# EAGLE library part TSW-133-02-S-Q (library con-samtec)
THROUGH-HOLE .025" SQ POST HEADER Source: Samtec TSW.pdf
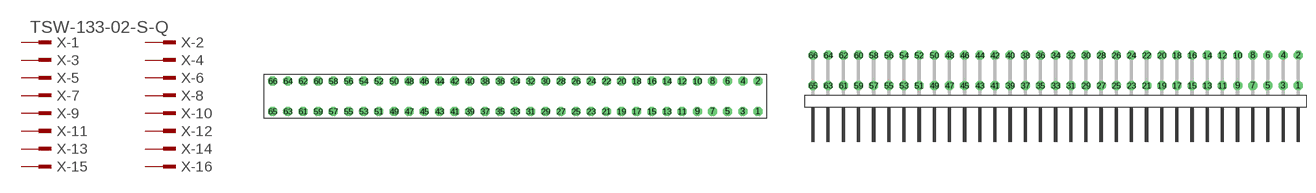
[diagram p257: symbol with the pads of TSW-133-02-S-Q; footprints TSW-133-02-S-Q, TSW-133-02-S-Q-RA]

Designator prefix X; gates -1=MPINV -2=MPIN -3=MPIN -4=MPIN -5=MPIN -6=MPIN -7=MPIN -8=MPIN -9=MPIN -10=MPIN -11=MPIN -12=MPIN -13=MPIN -14=MPIN -15=MPIN -16=MPIN -17=MPIN -18=MPIN -19=MPIN -20=MPIN -21=MPIN -22=MPIN -23=MPIN -24=MPIN -25=MPIN -26=MPIN -27=MPIN -28=MPIN -29=MPIN -30=MPIN -31=MPIN -32=MPIN -33=MPIN -34=MPIN -35=MPIN -36=MPIN -37=MPIN -38=MPIN -39=MPIN -40=MPIN -41=MPIN -42=MPIN -43=MPIN -44=MPIN -45=MPIN -46=MPIN -47=MPIN -48=MPIN -49=MPIN -50=MPIN -51=MPIN -52=MPIN -53=MPIN -54=MPIN -55=MPIN -56=MPIN -57=MPIN -58=MPIN -59=MPIN -60=MPIN -61=MPIN -62=MPIN -63=MPIN -64=MPIN -65=MPIN -66=MPIN

## TSW-133-02-S-Q (OC_FARNELL: unknown; OC_NEWARK: unknown)  [TSW-133-02-S-Q]
1  -1:1  pas
2  -2:1  pas
3  -3:1  pas
4  -4:1  pas
5  -5:1  pas
6  -6:1  pas
7  -7:1  pas
8  -8:1  pas
9  -9:1  pas
10  -10:1  pas
11  -11:1  pas
12  -12:1  pas
13  -13:1  pas
14  -14:1  pas
15  -15:1  pas
16  -16:1  pas
17  -17:1  pas
18  -18:1  pas
19  -19:1  pas
20  -20:1  pas
21  -21:1  pas
22  -22:1  pas
23  -23:1  pas
24  -24:1  pas
25  -25:1  pas
26  -26:1  pas
27  -27:1  pas
28  -28:1  pas
29  -29:1  pas
30  -30:1  pas
31  -31:1  pas
32  -32:1  pas
33  -33:1  pas
34  -34:1  pas
35  -35:1  pas
36  -36:1  pas
37  -37:1  pas
38  -38:1  pas
39  -39:1  pas
40  -40:1  pas
41  -41:1  pas
42  -42:1  pas
43  -43:1  pas
44  -44:1  pas
45  -45:1  pas
46  -46:1  pas
47  -47:1  pas
48  -48:1  pas
49  -49:1  pas
50  -50:1  pas
51  -51:1  pas
52  -52:1  pas
53  -53:1  pas
54  -54:1  pas
55  -55:1  pas
56  -56:1  pas
57  -57:1  pas
58  -58:1  pas
59  -59:1  pas
60  -60:1  pas
61  -61:1  pas
62  -62:1  pas
63  -63:1  pas
64  -64:1  pas
65  -65:1  pas
66  -66:1  pas

## TSW-133-02-S-Q-RA (OC_FARNELL: unknown; OC_NEWARK: unknown)  [TSW-133-02-S-Q-RA]
Pads as for TSW-133-02-S-Q

## Footprint TSW-133-02-S-Q (pad centres in mm)
THROUGH-HOLE .025" SQ POST HEADER Source: Samtec TSW.pdf
drill 1 pad 1.5 octagon: 1 40.64,-2.54; 2 40.64,2.54; 3 38.1,-2.54; 4 38.1,2.54; 5 35.56,-2.54; 6 35.56,2.54; 7 33.02,-2.54; 8 33.02,2.54; 9 30.48,-2.54; 10 30.48,2.54; 11 27.94,-2.54; 12 27.94,2.54; 13 25.4,-2.54; 14 25.4,2.54; 15 22.86,-2.54; 16 22.86,2.54; 17 20.32,-2.54; 18 20.32,2.54; 19 17.78,-2.54; 20 17.78,2.54; 21 15.24,-2.54; 22 15.24,2.54; 23 12.7,-2.54; 24 12.7,2.54; 25 10.16,-2.54; 26 10.16,2.54; 27 7.62,-2.54; 28 7.62,2.54; 29 5.08,-2.54; 30 5.08,2.54; 31 2.54,-2.54; 32 2.54,2.54; 33 0,-2.54; 34 0,2.54; 35 -2.54,-2.54; 36 -2.54,2.54; 37 -5.08,-2.54; 38 -5.08,2.54; 39 -7.62,-2.54; 40 -7.62,2.54; 41 -10.16,-2.54; 42 -10.16,2.54; 43 -12.7,-2.54; 44 -12.7,2.54; 45 -15.24,-2.54; 46 -15.24,2.54; 47 -17.78,-2.54; 48 -17.78,2.54; 49 -20.32,-2.54; 50 -20.32,2.54; 51 -22.86,-2.54; 52 -22.86,2.54; 53 -25.4,-2.54; 54 -25.4,2.54; 55 -27.94,-2.54; 56 -27.94,2.54; 57 -30.48,-2.54; 58 -30.48,2.54; 59 -33.02,-2.54; 60 -33.02,2.54; 61 -35.56,-2.54; 62 -35.56,2.54; 63 -38.1,-2.54; 64 -38.1,2.54; 65 -40.64,-2.54; 66 -40.64,2.54

## Footprint TSW-133-02-S-Q-RA (pad centres in mm)
THROUGH-HOLE .025" SQ POST HEADER Source: Samtec TSW.pdf
drill 1 pad 1.5 octagon: 1 40.64,1.524; 2 40.64,6.604; 3 38.1,1.524; 4 38.1,6.604; 5 35.56,1.524; 6 35.56,6.604; 7 33.02,1.524; 8 33.02,6.604; 9 30.48,1.524; 10 30.48,6.604; 11 27.94,1.524; 12 27.94,6.604; 13 25.4,1.524; 14 25.4,6.604; 15 22.86,1.524; 16 22.86,6.604; 17 20.32,1.524; 18 20.32,6.604; 19 17.78,1.524; 20 17.78,6.604; 21 15.24,1.524; 22 15.24,6.604; 23 12.7,1.524; 24 12.7,6.604; 25 10.16,1.524; 26 10.16,6.604; 27 7.62,1.524; 28 7.62,6.604; 29 5.08,1.524; 30 5.08,6.604; 31 2.54,1.524; 32 2.54,6.604; 33 0,1.524; 34 0,6.604; 35 -2.54,1.524; 36 -2.54,6.604; 37 -5.08,1.524; 38 -5.08,6.604; 39 -7.62,1.524; 40 -7.62,6.604; 41 -10.16,1.524; 42 -10.16,6.604; 43 -12.7,1.524; 44 -12.7,6.604; 45 -15.24,1.524; 46 -15.24,6.604; 47 -17.78,1.524; 48 -17.78,6.604; 49 -20.32,1.524; 50 -20.32,6.604; 51 -22.86,1.524; 52 -22.86,6.604; 53 -25.4,1.524; 54 -25.4,6.604; 55 -27.94,1.524; 56 -27.94,6.604; 57 -30.48,1.524; 58 -30.48,6.604; 59 -33.02,1.524; 60 -33.02,6.604; 61 -35.56,1.524; 62 -35.56,6.604; 63 -38.1,1.524; 64 -38.1,6.604; 65 -40.64,1.524; 66 -40.64,6.604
